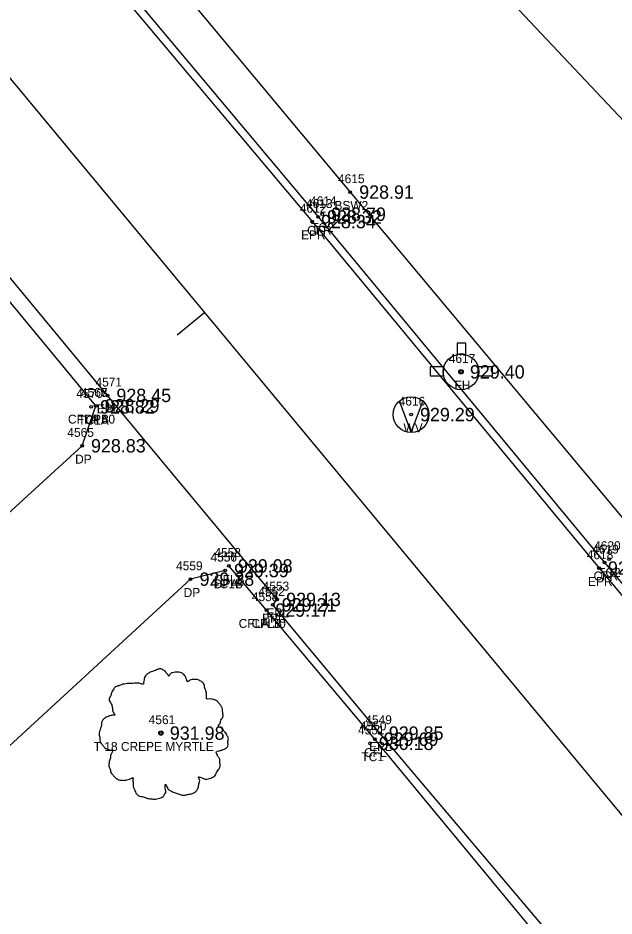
# Model space of a CAD drawing. Extents: x 1575382 to 1578175, y 1099175 to 1101955.
# Drawn here: x 1576287.4 to 1576354.3, y 1100077.2 to 1100177.9 of the extents above; entities that cross this region are included whole.
import ezdxf

# ---------------------------------------------------------------- set-up
doc = ezdxf.new("R2010")
doc.units = 0
for name, color, linetype in [('RD_EX_Conc', 7, 'Continuous'), ('RD_EX_Conc_txCode', 7, 'Continuous'), ('RD_EX_Driveway', 7, 'Continuous'), ('RD_EX_Driveway_txCode', 7, 'Continuous'), ('RD_EX_Road', 7, 'Continuous'), ('RD_EX_Road_txCode', 7, 'Continuous'), ('RD_EX_TX_Conc_ELEV', 7, 'Continuous'), ('RD_EX_TX_Driveway_ELEV', 7, 'Continuous'), ('RD_EX_TX_Road_ELEV', 7, 'Continuous'), ('RD_EX_TX_UT_ELEV', 7, 'Continuous'), ('RD_EX_TX_VEG_ELEV', 7, 'Continuous'), ('RD_EX_UT', 7, 'Continuous'), ('RD_EX_UT_txCode', 7, 'Continuous'), ('RD_EX_VEG', 7, 'Continuous'), ('RD_EX_VEG_txCode', 7, 'Continuous'), ('RD_HC_Cl', 7, 'Continuous'), ('RD_HC_Data_Tic', 7, 'Continuous'), ('RD_SMD_Locator', 7, 'Continuous')]:
    doc.layers.add(name, color=color, linetype=linetype)

msp = doc.modelspace()

# ---------------------------------------------------------------- linework, layer by layer
at = {"layer": 'RD_EX_Conc'}
for points in [[(1576260.63, 1100235.68), (1576292.32, 1100197.24), (1576324.7, 1100158.41), (1576356.89, 1100119.84), (1576388.53, 1100081.75), (1576417.29, 1100048.58), (1576453.09, 1100005.48), (1576485.23, 1099966.78), (1576516.75, 1099929.08), (1576537.53, 1099904.47)], [(1576256.92, 1100232.94), (1576288.76, 1100194.24), (1576321.1, 1100155.62), (1576353.2, 1100116.85), (1576384.81, 1100078.92)], [(1576296.17, 1100134.44), (1576268.52, 1100167.9), (1576263.22, 1100172.36), (1576257.48, 1100172.78), (1576253.76, 1100170.65)], [(1576370.77, 1100044.65), (1576358.48, 1100059.51), (1576327.45, 1100097.03), (1576315.3, 1100111.52), (1576315.3, 1100111.52), (1576311.1, 1100116.47)]]:
    msp.add_lwpolyline(points, dxfattribs=at)
at = {"layer": 'RD_EX_Driveway'}
for points in [[(1576256.46, 1100095.03), (1576294.63, 1100129.95), (1576296.17, 1100134.44)], [(1576310.67, 1100115.96), (1576306.8, 1100114.99), (1576274.61, 1100085.38)]]:
    msp.add_lwpolyline(points, dxfattribs=at)
at = {"layer": 'RD_EX_Road'}
for points in [[(1576256.11, 1100232.37), (1576288, 1100193.74), (1576320.42, 1100155.1), (1576352.59, 1100116.23), (1576384.18, 1100078.33), (1576416.49, 1100039.38), (1576447.98, 1100001.18), (1576479.99, 1099962.6), (1576511.56, 1099924.96), (1576536.28, 1099895.31), (1576544.58, 1099889.25), (1576552.5, 1099886.45), (1576559.41, 1099885.67), (1576563.94, 1099885.9), (1576563.8, 1099887.09)], [(1576526.76, 1099857.36), (1576527.6, 1099858), (1576488.54, 1099905.39), (1576460.88, 1099939.06), (1576418.27, 1099989.97), (1576392.95, 1100020.59), (1576359.55, 1100060.38), (1576328.02, 1100097.72), (1576316.02, 1100112.1), (1576316.51, 1100112.71), (1576297.48, 1100135.6), (1576269.79, 1100169.04), (1576232.76, 1100213.96)]]:
    msp.add_lwpolyline(points, dxfattribs=at)
at = {"layer": 'RD_EX_UT'}
for p, q in [((1576336.67, 1100141.46), (1576336.67, 1100140.19)), ((1576337.67, 1100141.46), (1576336.67, 1100141.46)), ((1576337.67, 1100140.17), (1576337.67, 1100141.46)), ((1576335.21, 1100138.81), (1576333.65, 1100138.81)), ((1576333.65, 1100138.81), (1576333.65, 1100137.81)), ((1576340.65, 1100138.81), (1576339.04, 1100138.81)), ((1576340.65, 1100137.81), (1576340.65, 1100138.81)), ((1576333.65, 1100137.81), (1576335.17, 1100137.81)), ((1576339.08, 1100137.81), (1576340.65, 1100137.81)), ((1576331.52, 1100131.46), (1576330.22, 1100134.94)), ((1576331.52, 1100131.46), (1576332.85, 1100134.9))]:
    msp.add_line(p, q, dxfattribs=at)
msp.add_lwpolyline([(1576420.44, 1100010.19), (1576451.56, 1100064.3), (1576214.56, 1100315.75)], dxfattribs=at)
for centre, radius in [((1576337.12, 1100138.24), 2), ((1576337.12, 1100138.24), 0.25), ((1576331.52, 1100133.45), 2)]:
    msp.add_circle(centre, radius, dxfattribs=at)
for start, end in [(74.2455, 103.2128), (163.3387, 192.315), (347.685, 16.6613)]:
    msp.add_arc((1576337.12, 1100138.24), 2, start, end, dxfattribs=at)
at = {"layer": 'RD_EX_VEG'}
for centre, radius in [((1576303.47, 1100097.72), 0.25), ((1576303.46, 1100097.7), 0.0001)]:
    msp.add_circle(centre, radius, dxfattribs=at)
for points in [[(1576303.61, 1100104.89), (1576303.31, 1100104.91), (1576302.98, 1100104.81), (1576302.73, 1100104.71), (1576302.51, 1100104.64), (1576302.28, 1100104.54), (1576301.98, 1100104.36), (1576301.76, 1100104.16), (1576301.63, 1100103.91), (1576301.58, 1100103.69), (1576301.53, 1100103.41), (1576301.53, 1100103.24), (1576301.41, 1100103.21), (1576301.26, 1100103.24), (1576301.01, 1100103.31), (1576300.76, 1100103.31), (1576300.51, 1100103.31), (1576300.16, 1100103.29), (1576299.81, 1100103.29), (1576299.53, 1100103.24), (1576299.21, 1100103.19), (1576298.83, 1100103.06), (1576298.48, 1100102.94), (1576298.18, 1100102.69), (1576297.93, 1100102.21), (1576297.81, 1100101.86), (1576297.66, 1100101.61), (1576297.81, 1100101.16), (1576297.98, 1100100.81), (1576298.01, 1100100.61), (1576298.08, 1100100.19), (1576298.18, 1100099.96), (1576298.31, 1100099.76), (1576298.23, 1100099.74), (1576297.86, 1100099.69), (1576297.56, 1100099.59), (1576297.13, 1100099.36), (1576296.91, 1100099.14), (1576296.81, 1100098.81), (1576296.78, 1100098.46), (1576296.68, 1100098.26), (1576296.61, 1100097.99), (1576296.58, 1100097.91), (1576296.53, 1100097.59), (1576296.63, 1100097.14), (1576296.66, 1100096.79), (1576296.78, 1100096.56), (1576296.93, 1100096.39), (1576297.11, 1100096.14), (1576297.51, 1100095.91), (1576297.83, 1100095.81), (1576298.03, 1100095.79), (1576297.86, 1100095.29), (1576297.81, 1100094.94), (1576297.68, 1100094.54), (1576297.68, 1100094.46), (1576297.63, 1100093.99), (1576297.78, 1100093.67), (1576297.86, 1100093.29), (1576298.03, 1100093.07), (1576298.31, 1100092.77), (1576298.63, 1100092.54), (1576299.13, 1100092.42), (1576299.53, 1100092.44), (1576300.11, 1100092.62), (1576300.36, 1100092.69), (1576300.33, 1100092.52), (1576300.36, 1100092.14), (1576300.36, 1100091.72), (1576300.51, 1100091.39), (1576300.61, 1100091.12), (1576300.76, 1100090.87), (1576301.08, 1100090.64), (1576301.48, 1100090.57), (1576301.91, 1100090.42), (1576302.36, 1100090.34), (1576302.86, 1100090.32), (1576303.46, 1100090.47), (1576303.73, 1100090.59), (1576303.83, 1100090.77), (1576304.03, 1100091.14), (1576303.98, 1100091.37), (1576304.01, 1100091.97), (1576304.11, 1100091.79), (1576304.28, 1100091.44), (1576304.78, 1100091.14), (1576305.18, 1100090.97), (1576305.65, 1100090.82), (1576305.95, 1100090.74), (1576306.43, 1100090.82), (1576306.8, 1100090.89), (1576307.18, 1100091.02), (1576307.48, 1100091.29), (1576307.65, 1100091.57), (1576307.7, 1100091.84), (1576307.78, 1100092.22), (1576307.83, 1100092.39)], [(1576307.83, 1100092.39), (1576307.75, 1100092.57), (1576307.7, 1100092.82), (1576307.78, 1100092.79), (1576307.95, 1100092.74), (1576308.23, 1100092.62), (1576308.45, 1100092.54), (1576308.78, 1100092.57), (1576309.05, 1100092.67), (1576309.5, 1100092.94), (1576309.78, 1100093.42), (1576310.05, 1100093.82), (1576310.13, 1100094.14), (1576310.08, 1100094.36), (1576310.05, 1100094.86), (1576309.85, 1100095.11), (1576309.8, 1100095.24), (1576309.7, 1100095.64), (1576309.78, 1100095.69), (1576310.05, 1100095.74), (1576310.43, 1100095.86), (1576310.7, 1100095.99), (1576310.93, 1100096.16), (1576311, 1100096.39), (1576310.98, 1100096.79), (1576311.03, 1100097.19), (1576310.95, 1100097.34), (1576310.85, 1100097.49), (1576310.78, 1100097.69), (1576310.63, 1100097.84), (1576310.53, 1100097.99), (1576310.43, 1100098.09), (1576310.3, 1100098.24), (1576310.13, 1100098.36), (1576309.98, 1100098.41), (1576309.93, 1100098.56), (1576310.08, 1100098.76), (1576310.13, 1100098.86), (1576310.15, 1100099.09), (1576310.38, 1100099.44), (1576310.43, 1100099.84), (1576310.38, 1100100.26), (1576310.33, 1100100.54), (1576310.18, 1100100.81), (1576309.98, 1100101.06), (1576309.85, 1100101.24), (1576309.68, 1100101.36), (1576309.35, 1100101.49), (1576309.1, 1100101.54), (1576308.75, 1100101.54), (1576308.55, 1100101.59), (1576308.58, 1100101.64), (1576308.58, 1100101.79), (1576308.58, 1100102.06), (1576308.5, 1100102.51), (1576308.35, 1100103.01), (1576308.35, 1100103.04), (1576308.25, 1100103.29), (1576308.03, 1100103.49), (1576307.85, 1100103.59), (1576307.65, 1100103.71), (1576307.4, 1100103.74), (1576307.1, 1100103.74), (1576306.83, 1100103.69), (1576306.63, 1100103.59), (1576306.45, 1100103.46), (1576306.38, 1100103.61), (1576306.28, 1100103.91), (1576306.23, 1100104.06), (1576306.08, 1100104.24), (1576305.85, 1100104.44), (1576305.4, 1100104.56), (1576304.78, 1100104.49), (1576304.48, 1100104.29), (1576304.33, 1100104.11), (1576304.28, 1100104.24), (1576304.08, 1100104.44), (1576303.98, 1100104.61), (1576303.81, 1100104.74), (1576303.66, 1100104.84), (1576303.56, 1100104.89)]]:
    msp.add_spline(points, degree=3, dxfattribs=at)
at = {"layer": 'RD_HC_Cl'}
msp.add_line((1576563.81, 1099837.07), (1576243.36, 1100223.24), dxfattribs=at)
at = {"layer": 'RD_HC_Data_Tic'}
msp.add_line((1576308.38, 1100144.89), (1576305.3, 1100142.34), dxfattribs=at)
at = {"layer": 'RD_SMD_Locator'}
for centre in [(1576324.7, 1100158.41), (1576321.1, 1100155.62), (1576321.56, 1100155.93), (1576320.42, 1100155.1), (1576337.12, 1100138.24), (1576297.48, 1100135.6), (1576295.65, 1100134.32), (1576296.17, 1100134.44), (1576296.17, 1100134.44), (1576331.52, 1100133.45), (1576294.63, 1100129.95), (1576353.74, 1100117.24), (1576310.67, 1100115.96), (1576310.67, 1100115.96), (1576311.1, 1100116.47), (1576352.59, 1100116.23), (1576353.2, 1100116.85), (1576306.8, 1100114.99), (1576316.02, 1100112.1), (1576316.51, 1100112.71), (1576315.3, 1100111.52), (1576315.3, 1100111.52), (1576303.47, 1100097.72), (1576327.45, 1100097.03), (1576328.02, 1100097.72), (1576326.91, 1100096.57)]:
    msp.add_circle(centre, 0.15, dxfattribs=at)

# ---------------------------------------------------------------- texts
at = {"layer": 'RD_EX_Conc_txCode'}
for s, p in [('4615', (1576323.33, 1100159.41)), ('4613', (1576319.73, 1100156.62)), ('4614', (1576320.19, 1100156.93)), ('BSW2', (1576322.93, 1100156.41)), ('CFR', (1576319.87, 1100153.62)), ('TC2', (1576320.32, 1100153.93)), ('4570', (1576293.98, 1100135.32)), ('4568', (1576294.51, 1100135.44)), ('CFLA 30', (1576293.05, 1100132.44)), ('TC1A', (1576294.2, 1100132.32)), ('4620', (1576352.04, 1100118.24)), ('4558', (1576309.47, 1100117.47)), ('4619', (1576351.83, 1100117.85)), ('4556', (1576309.02, 1100116.96)), ('TC2', (1576352.49, 1100115.24)), ('CFLB', (1576309.43, 1100114.47)), ('CFR', (1576351.98, 1100114.85)), ('TC1B', (1576309.24, 1100113.96)), ('4554', (1576313.67, 1100112.52)), ('4555', (1576313.67, 1100112.52)), ('CFLA 30', (1576312.19, 1100109.52)), ('CFLB', (1576313.63, 1100109.52)), ('4550', (1576325.78, 1100098.03)), ('4551', (1576325.57, 1100097.57)), ('CFL', (1576326.25, 1100095.03)), ('TC1', (1576325.95, 1100094.57))]:
    msp.add_text(s, height=1, dxfattribs=at).set_placement(p)
at = {"layer": 'RD_EX_Driveway_txCode'}
for s, p in [('4567', (1576294.51, 1100135.44)), ('DPB', (1576294.91, 1100132.44)), ('4565', (1576292.98, 1100130.95)), ('DP', (1576293.85, 1100127.95)), ('4557', (1576309.04, 1100116.96)), ('4559', (1576305.17, 1100115.99)), ('DPA', (1576309.4, 1100113.96)), ('DP', (1576306.02, 1100112.99))]:
    msp.add_text(s, height=1, dxfattribs=at).set_placement(p)
at = {"layer": 'RD_EX_Road_txCode'}
for s, p in [('4612', (1576319.05, 1100156.1)), ('EPR', (1576319.19, 1100153.1)), ('4571', (1576296.14, 1100136.6)), ('EPL', (1576296.28, 1100133.6)), ('4618', (1576351.22, 1100117.23)), ('EPR', (1576351.36, 1100114.23)), ('4552', (1576314.39, 1100113.1)), ('4553', (1576314.88, 1100113.71)), ('EPL', (1576314.82, 1100110.1)), ('EPL', (1576315.3, 1100110.71)), ('4549', (1576326.39, 1100098.72)), ('EPL', (1576326.82, 1100095.72))]:
    msp.add_text(s, height=1, dxfattribs=at).set_placement(p)
at = {"layer": 'RD_EX_TX_Conc_ELEV'}
for s, p in [('928.91', (1576325.7, 1100157.66)), ('928.32', (1576322.1, 1100154.87)), ('928.79', (1576322.56, 1100155.18)), ('928.29', (1576297.17, 1100133.69)), ('928.82', (1576296.65, 1100133.57)), ('929.08', (1576312.1, 1100115.72)), ('929.39', (1576311.67, 1100115.21)), ('929.17', (1576316.3, 1100110.77)), ('929.17', (1576316.3, 1100110.77)), ('930.18', (1576327.91, 1100095.82)), ('929.69', (1576328.45, 1100096.28))]:
    msp.add_text(s, height=1.5, dxfattribs=at).set_placement(p)
at = {"layer": 'RD_EX_TX_Driveway_ELEV'}
for s, p in [('928.29', (1576297.17, 1100133.69)), ('928.83', (1576295.63, 1100129.2)), ('929.39', (1576311.67, 1100115.21)), ('929.28', (1576307.8, 1100114.24))]:
    msp.add_text(s, height=1.5, dxfattribs=at).set_placement(p)
at = {"layer": 'RD_EX_TX_Road_ELEV'}
for s, p in [('928.34', (1576321.42, 1100154.35)), ('928.45', (1576298.48, 1100134.85)), ('929.68', (1576353.59, 1100115.48)), ('929.13', (1576317.51, 1100111.96)), ('929.21', (1576317.02, 1100111.35)), ('929.85', (1576329.02, 1100096.97))]:
    msp.add_text(s, height=1.5, dxfattribs=at).set_placement(p)
at = {"layer": 'RD_EX_TX_UT_ELEV'}
for s, p in [('929.40', (1576338.12, 1100137.49)), ('929.29', (1576332.52, 1100132.7))]:
    msp.add_text(s, height=1.5, dxfattribs=at).set_placement(p)
at = {"layer": 'RD_EX_TX_VEG_ELEV'}
msp.add_text('931.98', height=1.5, dxfattribs=at).set_placement((1576304.47, 1100096.97))
at = {"layer": 'RD_EX_UT_txCode'}
for s, p in [('4617', (1576335.75, 1100139.24)), ('FH', (1576336.39, 1100136.24)), ('4616', (1576330.13, 1100134.45)), ('WV', (1576330.67, 1100131.45))]:
    msp.add_text(s, height=1, dxfattribs=at).set_placement(p)
at = {"layer": 'RD_EX_VEG_txCode'}
for s, p in [('4561', (1576302.1, 1100098.72)), ('T 18 CREPE MYRTLE', (1576295.94, 1100095.72))]:
    msp.add_text(s, height=1, dxfattribs=at).set_placement(p)

doc.saveas('drawing.dxf')
